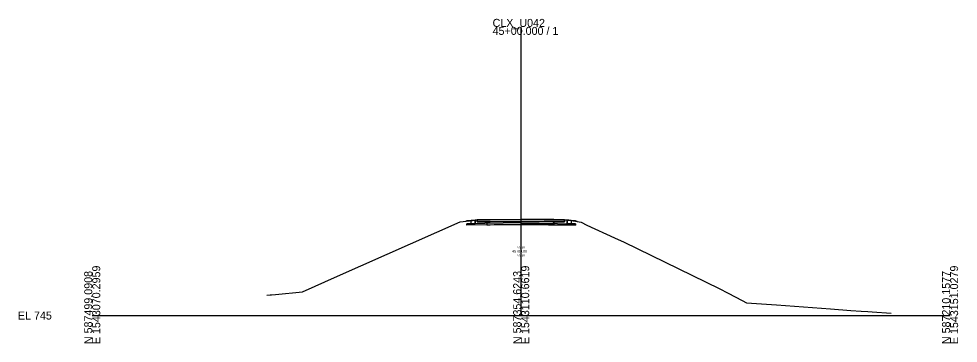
# Model space of a CAD drawing. Extents: x -26 to 1603, y -10 to 5557.
# Drawn here: x -25.7 to 302.8, y 1990.3 to 2103.9 of the extents above; entities that cross this region are included whole.
import ezdxf

# ---------------------------------------------------------------- set-up
doc = ezdxf.new("R2010")
doc.units = 0
for name, color, linetype in [('GK_Cells', 7, 'Continuous'), ('XS_P_Annotation', 7, 'Continuous'), ('XS_P_Earthwork_Shapes', 7, 'Continuous'), ('XS_P_Finished_Grade', 7, 'Continuous'), ('XS_P_Pavt_Layers', 7, 'Continuous'), ('XS_P_Pavt_Surface', 7, 'Continuous'), ('XS_P_Subgrade', 7, 'Continuous'), ('XS_X_Ground_Line', 7, 'Continuous'), ('XS_X_Pavt', 7, 'Continuous')]:
    doc.layers.add(name, color=color, linetype=linetype)

msp = doc.modelspace()

# ---------------------------------------------------------------- linework, layer by layer
at = {"layer": 'GK_Cells'}
for p, q in [((150, 2000), (150, 2101.05)), ((0, 2000), (150, 2000)), ((150, 2000), (300, 2000))]:
    msp.add_line(p, q, dxfattribs=at)
at = {"layer": 'XS_P_Earthwork_Shapes'}
for points in [[(134.59, 2032.75), (136.97, 2032.78), (138.02, 2032.79), (138.18, 2032.79), (139.17, 2032.8), (149.77, 2032.93), (161.12, 2032.82), (161.45, 2032.82), (165.2, 2032.77), (165.21, 2032.77), (165.21, 2033.52), (165.2, 2033.52), (161.45, 2033.57), (161.12, 2033.57), (149.77, 2033.68), (139.17, 2033.55), (138.18, 2033.54), (136.97, 2033.53), (134.59, 2033.5)], [(134.59, 2032.75), (136.97, 2032.78), (138.02, 2032.79), (138.18, 2032.79), (139.17, 2032.8), (149.77, 2032.93), (161.12, 2032.82), (161.45, 2032.82), (165.2, 2032.77), (165.21, 2032.77), (165.21, 2033.52), (165.2, 2033.52), (161.45, 2033.57), (161.12, 2033.57), (149.77, 2033.68), (139.17, 2033.55), (138.18, 2033.54), (136.97, 2033.53), (134.59, 2033.5)], [(134.59, 2033.5), (136.97, 2033.53), (138.18, 2033.54), (139.17, 2033.55), (149.77, 2033.68), (161.12, 2033.57), (161.45, 2033.57), (165.2, 2033.52), (165.21, 2033.52), (165.21, 2032.77), (165.2, 2032.77), (161.45, 2032.82), (161.12, 2032.82), (149.77, 2032.93), (139.17, 2032.8), (138.18, 2032.79), (138.02, 2032.79), (136.97, 2032.78), (134.59, 2032.75)], [(130.7, 2033.03), (133.01, 2033.31), (133.9, 2033.42), (131, 2033.18)], [(130.7, 2033.03), (133.01, 2033.31), (133.9, 2033.42), (131, 2033.18)], [(132.5, 2033.25), (132.5, 2033.3), (131, 2033.18), (130.7, 2033.03)], [(134.52, 2033.5), (134.59, 2033.5), (134.59, 2032.75), (136.97, 2032.78), (138.02, 2032.79), (138.02, 2031.79), (138.18, 2031.79), (139.17, 2031.8), (149.77, 2031.93), (150, 2031.93), (131, 2031.63), (131, 2032.13), (132.5, 2032.15), (132.5, 2033.25), (133.01, 2033.31)], [(134.59, 2032.75), (136.97, 2032.78), (138.02, 2032.79), (138.02, 2031.79), (138.18, 2031.79), (139.17, 2031.8), (149.77, 2031.93), (150, 2031.93), (131, 2031.63), (131, 2032.13), (133.9, 2032.17), (133.9, 2033.42), (134.52, 2033.5), (134.59, 2033.5)], [(133.9, 2033.42), (134.52, 2033.5), (134.59, 2033.5), (134.59, 2032.75), (136.97, 2032.78), (138.02, 2032.79), (138.02, 2031.79), (138.18, 2031.79), (139.17, 2031.8), (149.77, 2031.93), (150, 2031.93), (131, 2031.63), (131, 2032.13), (133.9, 2032.17)], [(138.18, 2031.79), (139.17, 2031.8), (149.77, 2031.93), (150, 2031.93), (161.12, 2031.82), (161.45, 2031.82), (161.45, 2032.82), (161.12, 2032.82), (149.77, 2032.93), (139.17, 2032.8), (138.18, 2032.79), (138.02, 2032.79), (138.02, 2031.79)], [(138.18, 2031.79), (139.17, 2031.8), (149.77, 2031.93), (150, 2031.93), (161.12, 2031.82), (161.45, 2031.82), (161.45, 2032.82), (161.12, 2032.82), (149.77, 2032.93), (139.17, 2032.8), (138.18, 2032.79), (138.02, 2032.79), (138.02, 2031.79)], [(138.18, 2031.79), (139.17, 2031.8), (149.77, 2031.93), (150, 2031.93), (161.12, 2031.82), (161.45, 2031.82), (161.45, 2032.82), (161.12, 2032.82), (149.77, 2032.93), (139.17, 2032.8), (138.18, 2032.79), (138.02, 2032.79), (138.02, 2031.79)], [(167.5, 2033.23), (167.5, 2032.15), (169, 2032.13), (169, 2031.63), (150, 2031.93), (161.12, 2031.82), (161.45, 2031.82), (161.45, 2032.82), (165.2, 2032.77), (165.21, 2032.77), (165.21, 2033.52), (166.62, 2033.37)], [(166.08, 2032.17), (169, 2032.13), (169, 2031.63), (150, 2031.93), (161.12, 2031.82), (161.45, 2031.82), (161.45, 2032.82), (165.2, 2032.77), (165.21, 2032.77), (165.21, 2033.52), (166.08, 2033.42)], [(165.21, 2033.52), (165.21, 2032.77), (165.2, 2032.77), (161.45, 2032.82), (161.45, 2031.82), (161.12, 2031.82), (150, 2031.93), (169, 2031.63), (169, 2032.13), (166.08, 2032.17), (166.08, 2033.42)], [(166.08, 2033.42), (169, 2033.18), (169.54, 2032.91), (169.04, 2032.99), (166.62, 2033.37)], [(166.08, 2033.42), (169, 2033.18), (169.54, 2032.91), (169.04, 2032.99), (166.62, 2033.37)], [(167.5, 2033.23), (169.04, 2032.99), (169.54, 2032.91), (169, 2033.18), (167.5, 2033.3)]]:
    msp.add_lwpolyline(points, close=True, dxfattribs=at)
at = {"layer": 'XS_P_Finished_Grade'}
for p, q in [((131, 2033.18), (130.7, 2033.03)), ((133.9, 2033.42), (131, 2033.18)), ((166.08, 2033.42), (169, 2033.18)), ((169, 2033.18), (169.54, 2032.91))]:
    msp.add_line(p, q, dxfattribs=at)
at = {"layer": 'XS_P_Pavt_Layers'}
for p, q in [((150.02, 2032.43), (131, 2032.13)), ((131, 2031.63), (131, 2032.13)), ((150.03, 2031.93), (131, 2031.63)), ((133.9, 2033.42), (133.9, 2032.17)), ((149.97, 2031.93), (169, 2031.63)), ((149.98, 2032.43), (169, 2032.13)), ((166.08, 2033.42), (166.08, 2032.17)), ((169, 2031.63), (169, 2032.13))]:
    msp.add_line(p, q, dxfattribs=at)
at = {"layer": 'XS_P_Pavt_Surface'}
for q in [(134, 2033.43), (166, 2033.43)]:
    msp.add_line((150, 2033.68), q, dxfattribs=at)
at = {"layer": 'XS_P_Subgrade'}
msp.add_lwpolyline([(166.08, 2033.42), (166.08, 2032.17), (169, 2032.13), (169, 2031.63), (150, 2031.93), (131, 2031.63), (131, 2032.13), (133.9, 2032.17), (133.9, 2033.42)], dxfattribs=at)
at = {"layer": 'XS_X_Ground_Line'}
msp.add_lwpolyline([(61.1, 2007.12), (62.24, 2007.23), (62.72, 2007.27), (64.04, 2007.4), (73.52, 2008.31), (85.79, 2013.79), (128.68, 2032.77), (133.01, 2033.31), (134.52, 2033.5), (136.97, 2033.53), (138.18, 2033.54), (139.17, 2033.55), (149.77, 2033.68), (161.12, 2033.57), (161.45, 2033.57), (165.2, 2033.52), (166.62, 2033.37), (169.04, 2032.99), (170.97, 2032.68), (172.95, 2031.64), (182.69, 2027.18), (185.99, 2025.67), (219.23, 2009.45), (222.39, 2007.82), (227.24, 2005.32), (228.82, 2004.5), (239.3, 2003.73), (258.2, 2002.34), (265.25, 2001.82), (268.93, 2001.55), (271.2, 2001.39), (272.73, 2001.27), (279.43, 2000.82)], dxfattribs=at)
at = {"layer": 'XS_X_Pavt'}
for p, q in [((134.59, 2033.5), (134.59, 2032.75)), ((134.59, 2032.75), (136.97, 2032.78)), ((136.97, 2032.78), (138.02, 2032.79)), ((138.02, 2032.79), (138.18, 2032.79)), ((138.02, 2032.79), (138.02, 2031.79)), ((138.02, 2031.79), (138.18, 2031.79)), ((138.18, 2032.79), (139.17, 2032.8)), ((138.18, 2031.79), (139.17, 2031.8)), ((139.17, 2032.8), (149.77, 2032.93)), ((139.17, 2031.8), (149.77, 2031.93)), ((149.77, 2032.93), (161.12, 2032.82)), ((149.77, 2031.93), (161.12, 2031.82)), ((161.12, 2032.82), (161.45, 2032.82)), ((161.12, 2031.82), (161.45, 2031.82)), ((161.45, 2032.82), (161.46, 2032.82)), ((161.45, 2031.82), (161.46, 2031.82)), ((161.46, 2032.82), (165.2, 2032.77)), ((161.46, 2032.82), (161.46, 2031.82)), ((165.2, 2032.77), (165.21, 2032.77)), ((165.21, 2033.52), (165.21, 2032.77))]:
    msp.add_line(p, q, dxfattribs=at)

# ---------------------------------------------------------------- texts
at = {"layer": 'GK_Cells'}
for s, p in [('CLX_U042', (140, 2101.05)), ('45+00.000 / 1', (140, 2098.25)), ('EL 745', (-26, 1998.6))]:
    msp.add_text(s, height=2.8, dxfattribs=at).set_placement(p)
for s, p in [('E 1543070.2959', (2.8, 1990)), ('E 1543110.6619', (152.8, 1990)), ('E 1543151.0279', (302.8, 1990)), ('N 587499.0908', (0, 1990)), ('N 587354.6243', (150, 1990)), ('N 587210.1577', (300, 1990))]:
    msp.add_text(s, height=2.8, rotation=90, dxfattribs=at).set_placement(p)
at = {"layer": 'XS_P_Annotation'}
for s, height, p in [('778.68', 0.7, (148.31, 2023.55)), ('45+00.00', 0.9, (146.85, 2022.05)), ('778.68', 0.7, (148.31, 2020.75))]:
    msp.add_text(s, height=height, dxfattribs=at).set_placement(p)

doc.saveas('drawing.dxf')
